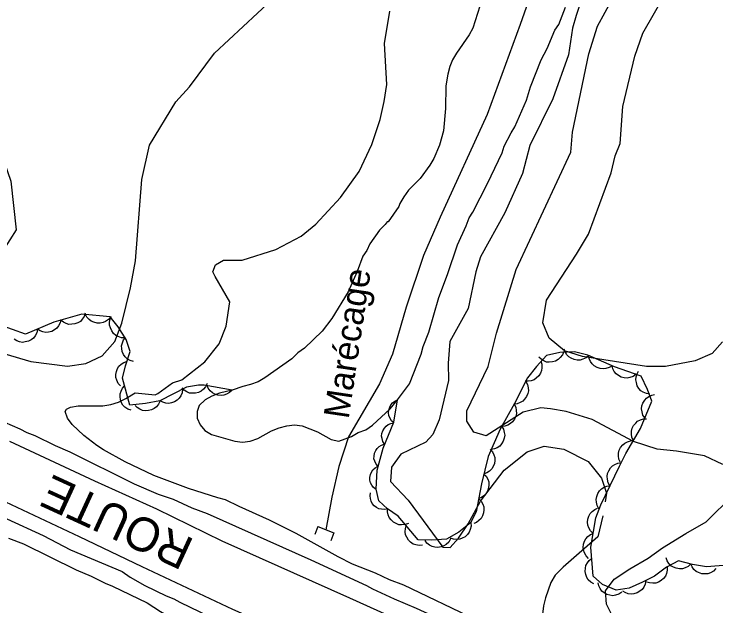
# Model space of a CAD drawing. Extents: x 282461 to 284471, y 5554090 to 5557646.
# Drawn here: x 283897.1 to 283980, y 5554845.7 to 5554915.8 of the extents above; entities that cross this region are included whole.
import ezdxf

# ---------------------------------------------------------------- set-up
doc = ezdxf.new("R2010")
doc.units = 0
for name, color, linetype in [('Niveau 1', 7, 'Continuous'), ('Niveau 15', 7, 'Continuous'), ('Niveau 2', 7, 'Continuous'), ('Niveau 21', 7, 'Continuous'), ('Niveau 26', 7, 'Continuous'), ('Niveau 4', 7, 'Continuous'), ('Niveau 44', 7, 'Continuous'), ('Niveau 7', 7, 'Continuous')]:
    doc.layers.add(name, color=color, linetype=linetype)

msp = doc.modelspace()

# ---------------------------------------------------------------- linework, layer by layer
at = {"layer": 'Niveau 1'}
for points in [[(283980.83, 5554862.48), (283978.67, 5554863.5), (283975.38, 5554864.07), (283973.1, 5554864.3), (283970.27, 5554865.21), (283965.39, 5554867.82), (283962.32, 5554868.73), (283960.5, 5554869.07), (283959.33, 5554869.19), (283957.26, 5554868.66), (283952.89, 5554865.88), (283951.4, 5554866.29), (283950.58, 5554867.62), (283950.61, 5554868.82), (283953.13, 5554874.08), (283954.08, 5554878), (283956.44, 5554885.54), (283962.88, 5554899.43), (283963.09, 5554901.8), (283965.03, 5554911.06), (283966.03, 5554914.34), (283969.64, 5554920.98)], [(283896.01, 5554875.58), (283899.08, 5554874.67), (283903.4, 5554874.1), (283905.57, 5554874.44), (283907.51, 5554875.34), (283909, 5554877.04), (283909.8, 5554879.19), (283910.85, 5554883.38), (283911.44, 5554886.56), (283912.17, 5554896.19), (283913.1, 5554900.26), (283916.2, 5554905.36), (283917.8, 5554907.17), (283920.78, 5554911.13), (283927.53, 5554917.47)], [(283895.94, 5554867.5), (283897.76, 5554866.71), (283898.61, 5554866.26), (283899.52, 5554865.92), (283901.96, 5554864.72), (283903.66, 5554863.99), (283911.27, 5554860.18), (283914.11, 5554858.99), (283915.87, 5554858.37), (283918.09, 5554857.35), (283919.9, 5554856.67), (283932.17, 5554851.22), (283938.75, 5554848.16), (283939.43, 5554847.76), (283941.99, 5554846.57), (283944.6, 5554845.49), (283949.76, 5554843.11), (283956.29, 5554839.94), (283960.54, 5554838.06), (283964.06, 5554836.7), (283969.28, 5554834.21), (283979.55, 5554830.13), (283986.92, 5554826.56)], [(283981.85, 5554840.18), (283979.81, 5554840.74), (283977.19, 5554841.31), (283973.67, 5554841.65), (283971.62, 5554842.11), (283969.13, 5554843.24), (283967.88, 5554844.37), (283967.09, 5554845.96), (283966.99, 5554847.55), (283968.02, 5554848.9), (283969.85, 5554850.15), (283972.01, 5554851.39), (283973.73, 5554852.64), (283976.46, 5554854.33), (283978.86, 5554855.69), (283982.06, 5554858.86)], [(283896.22, 5554856.06), (283900.54, 5554854.07), (283903.77, 5554852.37), (283909.85, 5554849.82), (283910.82, 5554849.14), (283912.52, 5554848.17), (283915.07, 5554846.93), (283915.98, 5554846.59), (283916.66, 5554846.19), (283922.45, 5554843.41)]]:
    msp.add_lwpolyline(points, dxfattribs=at)
at = {"layer": 'Niveau 2'}
for points in [[(283965.09, 5554920.31), (283963.51, 5554915.59), (283963.08, 5554914.09), (283962.61, 5554910.94), (283960.77, 5554905.74), (283958.02, 5554900.2), (283957.18, 5554896.9), (283955.09, 5554892.24), (283952.21, 5554887.06), (283951.64, 5554885.26), (283950.74, 5554880.94), (283948.59, 5554877.01), (283948.4, 5554874.46), (283948.42, 5554872.41), (283947.34, 5554867.78), (283946.56, 5554866.03), (283945.74, 5554865.13), (283942.78, 5554863.69), (283941.69, 5554862.17), (283941.59, 5554860.46), (283943.67, 5554858.26), (283947.75, 5554852.69), (283948.61, 5554852.68), (283949.61, 5554853.75), (283950.75, 5554855.46), (283952.21, 5554858.13), (283955.01, 5554861.79), (283957.71, 5554863.97), (283959.73, 5554864.65), (283962.06, 5554864.29), (283964.94, 5554862.84), (283966.52, 5554860.85), (283967.08, 5554859.08), (283966.94, 5554858.06)], [(283980.82, 5554876.98), (283979.58, 5554875.62), (283977.56, 5554874.73), (283974.06, 5554874.09), (283971.83, 5554874.09), (283964.28, 5554875.26), (283962.15, 5554875.93), (283960.31, 5554877.41), (283959.58, 5554879.25), (283960.01, 5554881.91), (283963.57, 5554887.35), (283964.98, 5554889.71), (283967.65, 5554896.98), (283968.13, 5554898.98), (283968.7, 5554900.43), (283969.03, 5554904.82), (283970.46, 5554910.77), (283971.39, 5554913.5), (283974, 5554918.07)], [(283911.39, 5554870.95), (283913.75, 5554870.72), (283914.07, 5554870.87), (283915.8, 5554872.14), (283916.9, 5554872.48), (283919.63, 5554874.62), (283921.32, 5554876.75), (283922.15, 5554878.86), (283922.59, 5554881.72), (283920.84, 5554884.71), (283920.59, 5554885.28), (283920.9, 5554886.08), (283921.82, 5554886.63), (283924.05, 5554886.63), (283928.01, 5554887.9), (283931, 5554889.47), (283932.75, 5554890.92), (283935.68, 5554894.07), (283937.87, 5554897.14), (283939.38, 5554900.33), (283940.34, 5554903.28), (283940.84, 5554905.42), (283941.15, 5554907.42), (283940.87, 5554912.27), (283941.48, 5554916.11)], [(283896.71, 5554895.98), (283897.34, 5554890.24), (283893.56, 5554884.32), (283891.96, 5554882.87), (283888.71, 5554882), (283886.03, 5554882.4), (283884.77, 5554882.94), (283883.11, 5554884.41), (283880.75, 5554888.18), (283878.69, 5554890.41), (283877.71, 5554891.75), (283877.13, 5554893.38), (283876.99, 5554894.78), (283877.15, 5554895.78), (283879.01, 5554898.91), (283882.64, 5554901.24), (283885.17, 5554902.21), (283886.65, 5554901.81), (283888.67, 5554900.5), (283891.61, 5554900.73), (283894.12, 5554900.14), (283895.53, 5554899.42), (283896.71, 5554895.98)], [(283951.68, 5554844.11), (283943.16, 5554848.19), (283941.46, 5554848.82), (283939.81, 5554849.61), (283937.08, 5554850.69), (283935.38, 5554851.54), (283930.44, 5554854.32), (283927.26, 5554855.91), (283923.68, 5554857.5), (283922.09, 5554858.3), (283921.18, 5554858.52), (283917.71, 5554859.66), (283913.61, 5554861.19), (283910.2, 5554862.78), (283907.65, 5554864.2), (283906.85, 5554864.72), (283905.32, 5554865.91), (283903.96, 5554867.21), (283903.4, 5554867.95), (283903.11, 5554868.74), (283903.29, 5554869.03), (283903.74, 5554869.25), (283904.66, 5554869.42), (283907.56, 5554869.42), (283908.53, 5554869.59), (283909.44, 5554869.87), (283910.3, 5554870.27), (283911.39, 5554870.95)], [(283966.67, 5554856.4), (283966.09, 5554853.92), (283961.96, 5554850.33)], [(283896.43, 5554853.78), (283898.19, 5554853.1), (283904.44, 5554850.03), (283906.2, 5554849.29), (283907.85, 5554848.44), (283908.7, 5554848.1), (283912.8, 5554846.12), (283914.39, 5554845.09), (283916.83, 5554843.67), (283918.53, 5554842.82), (283919.38, 5554842.48), (283920.97, 5554841.63), (283923.36, 5554839.99), (283924.83, 5554838.79)], [(283961.96, 5554850.33), (283961.04, 5554849.37), (283960.52, 5554848.52), (283959.89, 5554846.71), (283959.66, 5554845.75), (283959.54, 5554844.78)]]:
    msp.add_lwpolyline(points, dxfattribs=at)
at = {"layer": 'Niveau 21'}
for points in [[(283896.54, 5554865.24), (283906.59, 5554860.53), (283913.91, 5554857.24), (283921.63, 5554853.44), (283936.73, 5554846.7), (283965.15, 5554833.84), (284014.91, 5554811.14), (284025.97, 5554805.86)], [(283894.01, 5554859.02), (283904.79, 5554853.98), (283912.17, 5554850.4), (283922.9, 5554845.36), (283944.86, 5554835.61), (283957.34, 5554830.35), (283975.37, 5554822.08), (283983.99, 5554818.23), (284000.08, 5554810.69), (284009.04, 5554806.84), (284024.99, 5554799.62)]]:
    msp.add_lwpolyline(points, dxfattribs=at)
at = {"layer": 'Niveau 26'}
for p, q in [((283933, 5554855.13), (283932.63, 5554854.21)), ((283933, 5554855.13), (283934.88, 5554854.4)), ((283934.88, 5554854.4), (283934.51, 5554853.46))]:
    msp.add_line(p, q, dxfattribs=at)
at = {"layer": 'Niveau 4'}
msp.add_lwpolyline([(283962.58, 5554930.64), (283956.91, 5554914.53), (283952.99, 5554903.88), (283947.45, 5554891.74), (283945.49, 5554887.21), (283943.41, 5554881.08), (283941.79, 5554875.53), (283940.29, 5554872.01), (283936.61, 5554865.77), (283935.45, 5554862.26), (283934.63, 5554858.63), (283933.93, 5554854.77)], dxfattribs=at)
at = {"layer": 'Niveau 44'}
for points in [[(283922.84, 5554871.28), (283919.56, 5554871.88), (283918.88, 5554871.88), (283917.46, 5554871.62), (283914.31, 5554870), (283912.62, 5554869.69), (283910.75, 5554869.5), (283909.89, 5554872.69), (283910.26, 5554874.17), (283910.81, 5554875.83), (283910.33, 5554877.26), (283909.38, 5554878.75), (283908.43, 5554879.96), (283905.11, 5554880.27), (283901.8, 5554879.31), (283898.44, 5554877.88), (283895.32, 5554879.01)], [(283905.5, 5554880.38), (283905.38, 5554879.99), (283905.15, 5554879.66), (283904.92, 5554879.41), (283904.62, 5554879.23), (283904.28, 5554879.1), (283903.9, 5554879.06), (283903.57, 5554879.05), (283903.24, 5554879.16), (283902.91, 5554879.32), (283902.63, 5554879.55)], [(283908.5, 5554879.95), (283908.23, 5554879.63), (283907.89, 5554879.41), (283907.6, 5554879.26), (283907.25, 5554879.2), (283906.89, 5554879.21), (283906.52, 5554879.31), (283906.21, 5554879.42), (283905.94, 5554879.64), (283905.69, 5554879.92), (283905.52, 5554880.23)], [(283902.6, 5554879.65), (283902.52, 5554879.24), (283902.33, 5554878.88), (283902.14, 5554878.61), (283901.86, 5554878.4), (283901.53, 5554878.23), (283901.16, 5554878.14), (283900.84, 5554878.1), (283900.5, 5554878.16), (283900.15, 5554878.28), (283899.85, 5554878.48)], [(283910.2, 5554877.47), (283909.78, 5554877.48), (283909.4, 5554877.61), (283909.1, 5554877.75), (283908.84, 5554877.99), (283908.62, 5554878.28), (283908.47, 5554878.64), (283908.38, 5554878.95), (283908.38, 5554879.3), (283908.45, 5554879.66), (283908.59, 5554879.99)], [(283899.85, 5554878.48), (283899.77, 5554878.07), (283899.58, 5554877.71), (283899.39, 5554877.44), (283899.11, 5554877.23), (283898.78, 5554877.06), (283898.41, 5554876.97), (283898.09, 5554876.92), (283897.74, 5554876.99), (283897.4, 5554877.11), (283897.09, 5554877.31)], [(283911.2, 5554874.66), (283910.8, 5554874.77), (283910.46, 5554874.99), (283910.21, 5554875.2), (283910.01, 5554875.49), (283909.87, 5554875.83), (283909.81, 5554876.21), (283909.79, 5554876.53), (283909.88, 5554876.87), (283910.03, 5554877.21), (283910.25, 5554877.5)], [(283965, 5554875.38), (283964.69, 5554875.1), (283964.32, 5554874.93), (283964, 5554874.83), (283963.65, 5554874.83), (283963.28, 5554874.89), (283962.93, 5554875.05), (283962.65, 5554875.21), (283962.41, 5554875.47), (283962.21, 5554875.79), (283962.09, 5554876.13)], [(283982.43, 5554850.65), (283978.93, 5554850.37), (283977.28, 5554850.66), (283975.59, 5554851.07), (283974.17, 5554850.33), (283972.78, 5554849.28), (283971.36, 5554848.58), (283969.76, 5554847.85), (283968.26, 5554847.63), (283966.64, 5554848.28), (283965.52, 5554849.29), (283965.23, 5554852.71), (283965.84, 5554856.16), (283966.42, 5554857.69), (283968.62, 5554862.3), (283969.38, 5554863.78), (283971.13, 5554866.73), (283972.46, 5554869.96), (283971.95, 5554871.37), (283971.18, 5554872.94), (283968.05, 5554874.05), (283964.88, 5554875.41), (283963.32, 5554875.81), (283961.57, 5554875.72), (283960.02, 5554875.37), (283958.83, 5554874.09), (283957.78, 5554872.74), (283956.21, 5554869.68), (283954.53, 5554866.64), (283953.13, 5554863.41), (283952.34, 5554860.19), (283951.68, 5554856.89), (283951.03, 5554855.56), (283949.64, 5554854.49), (283948.18, 5554853.64), (283946.43, 5554853.52), (283944.84, 5554853.56), (283942.48, 5554856.37), (283941.23, 5554857.25)], [(283962.04, 5554875.83), (283961.88, 5554875.44), (283961.63, 5554875.12), (283961.39, 5554874.88), (283961.08, 5554874.72), (283960.73, 5554874.61), (283960.34, 5554874.59), (283960.02, 5554874.6), (283959.69, 5554874.73), (283959.37, 5554874.92), (283959.1, 5554875.16)], [(283967.76, 5554874.17), (283967.41, 5554873.95), (283967.02, 5554873.84), (283966.69, 5554873.79), (283966.34, 5554873.84), (283965.99, 5554873.96), (283965.66, 5554874.17), (283965.41, 5554874.37), (283965.21, 5554874.67), (283965.06, 5554875.01), (283964.99, 5554875.36)], [(283909.66, 5554871.77), (283909.38, 5554872.08), (283909.21, 5554872.45), (283909.11, 5554872.76), (283909.11, 5554873.11), (283909.17, 5554873.47), (283909.32, 5554873.82), (283909.48, 5554874.11), (283909.74, 5554874.34), (283910.05, 5554874.55), (283910.38, 5554874.67)], [(283959.33, 5554874.73), (283959.46, 5554874.33), (283959.46, 5554873.92), (283959.43, 5554873.59), (283959.29, 5554873.27), (283959.09, 5554872.96), (283958.8, 5554872.7), (283958.54, 5554872.5), (283958.21, 5554872.39), (283957.84, 5554872.33), (283957.48, 5554872.35)], [(283970.59, 5554873.15), (283970.25, 5554872.9), (283969.87, 5554872.77), (283969.54, 5554872.7), (283969.19, 5554872.73), (283968.83, 5554872.82), (283968.5, 5554873.01), (283968.23, 5554873.19), (283968.02, 5554873.48), (283967.84, 5554873.81), (283967.75, 5554874.16)], [(283972.23, 5554870.8), (283971.81, 5554870.86), (283971.44, 5554871.03), (283971.16, 5554871.21), (283970.93, 5554871.48), (283970.74, 5554871.79), (283970.63, 5554872.16), (283970.57, 5554872.48), (283970.62, 5554872.83), (283970.72, 5554873.19), (283970.9, 5554873.5)], [(283910.92, 5554868.89), (283910.52, 5554869.02), (283910.19, 5554869.26), (283909.95, 5554869.49), (283909.78, 5554869.79), (283909.65, 5554870.14), (283909.62, 5554870.52), (283909.62, 5554870.84), (283909.73, 5554871.17), (283909.9, 5554871.5), (283910.14, 5554871.77)], [(283919.89, 5554872.06), (283919.72, 5554871.68), (283919.46, 5554871.38), (283919.21, 5554871.16), (283918.89, 5554871.01), (283918.54, 5554870.91), (283918.16, 5554870.9), (283917.83, 5554870.93), (283917.51, 5554871.07), (283917.2, 5554871.27), (283916.95, 5554871.53)], [(283922.84, 5554871.28), (283922.55, 5554870.98), (283922.19, 5554870.79), (283921.89, 5554870.67), (283921.54, 5554870.64), (283921.17, 5554870.68), (283920.81, 5554870.81), (283920.52, 5554870.95), (283920.26, 5554871.19), (283920.04, 5554871.49), (283919.9, 5554871.82)], [(283957.56, 5554872.3), (283957.76, 5554871.94), (283957.84, 5554871.54), (283957.87, 5554871.21), (283957.79, 5554870.86), (283957.65, 5554870.52), (283957.42, 5554870.21), (283957.2, 5554869.97), (283956.89, 5554869.8), (283956.54, 5554869.67), (283956.18, 5554869.63)], [(283917, 5554871.38), (283916.95, 5554870.97), (283916.78, 5554870.6), (283916.61, 5554870.32), (283916.35, 5554870.08), (283916.04, 5554869.88), (283915.67, 5554869.77), (283915.36, 5554869.7), (283915.01, 5554869.74), (283914.65, 5554869.84), (283914.34, 5554870.01)], [(283941.23, 5554857.25), (283940.21, 5554858.19), (283939.88, 5554859.55), (283940, 5554861.82), (283940.7, 5554864.43), (283941.97, 5554867.49), (283942.39, 5554870.11)], [(283941.96, 5554867.4), (283941.68, 5554867.66), (283941.49, 5554867.98), (283941.38, 5554868.26), (283941.34, 5554868.58), (283941.37, 5554868.92), (283941.48, 5554869.25), (283941.61, 5554869.52), (283941.82, 5554869.76), (283942.09, 5554869.97), (283942.39, 5554870.11)], [(283971.64, 5554867.98), (283971.41, 5554868.33), (283971.3, 5554868.72), (283971.24, 5554869.05), (283971.29, 5554869.4), (283971.4, 5554869.75), (283971.61, 5554870.08), (283971.81, 5554870.33), (283972.1, 5554870.53), (283972.44, 5554870.69), (283972.79, 5554870.76)], [(283914.34, 5554870.01), (283914.17, 5554869.62), (283913.91, 5554869.32), (283913.66, 5554869.1), (283913.34, 5554868.95), (283912.99, 5554868.85), (283912.61, 5554868.84), (283912.28, 5554868.87), (283911.96, 5554869.01), (283911.65, 5554869.21), (283911.4, 5554869.47)], [(283956.18, 5554869.63), (283956.37, 5554869.25), (283956.44, 5554868.85), (283956.46, 5554868.52), (283956.37, 5554868.18), (283956.22, 5554867.84), (283955.98, 5554867.54), (283955.75, 5554867.31), (283955.44, 5554867.14), (283955.08, 5554867.03), (283954.72, 5554866.99)], [(283970.28, 5554865.3), (283970.11, 5554865.68), (283970.05, 5554866.09), (283970.04, 5554866.42), (283970.14, 5554866.76), (283970.3, 5554867.09), (283970.55, 5554867.38), (283970.78, 5554867.61), (283971.1, 5554867.76), (283971.46, 5554867.87), (283971.82, 5554867.89)], [(283940.88, 5554864.87), (283940.67, 5554865.19), (283940.57, 5554865.54), (283940.52, 5554865.84), (283940.56, 5554866.16), (283940.67, 5554866.48), (283940.85, 5554866.78), (283941.04, 5554867.02), (283941.3, 5554867.2), (283941.61, 5554867.34), (283941.93, 5554867.4)], [(283954.69, 5554867.01), (283954.92, 5554866.66), (283955.02, 5554866.26), (283955.07, 5554865.94), (283955.02, 5554865.59), (283954.9, 5554865.24), (283954.69, 5554864.91), (283954.48, 5554864.66), (283954.19, 5554864.47), (283953.85, 5554864.32), (283953.49, 5554864.25)], [(283968.75, 5554862.72), (283968.57, 5554863.1), (283968.51, 5554863.5), (283968.51, 5554863.83), (283968.6, 5554864.17), (283968.76, 5554864.5), (283969.01, 5554864.8), (283969.25, 5554865.02), (283969.57, 5554865.18), (283969.92, 5554865.28), (283970.28, 5554865.3)], [(283940.11, 5554862.24), (283939.86, 5554862.53), (283939.71, 5554862.87), (283939.62, 5554863.16), (283939.63, 5554863.48), (283939.68, 5554863.81), (283939.83, 5554864.13), (283939.98, 5554864.39), (283940.22, 5554864.6), (283940.51, 5554864.78), (283940.82, 5554864.89)], [(283953.35, 5554864.3), (283953.63, 5554863.99), (283953.8, 5554863.62), (283953.9, 5554863.3), (283953.91, 5554862.95), (283953.85, 5554862.58), (283953.7, 5554862.23), (283953.54, 5554861.95), (283953.28, 5554861.71), (283952.97, 5554861.5), (283952.63, 5554861.38)], [(283967.51, 5554859.97), (283967.3, 5554860.33), (283967.2, 5554860.73), (283967.17, 5554861.06), (283967.23, 5554861.4), (283967.36, 5554861.75), (283967.58, 5554862.07), (283967.8, 5554862.31), (283968.1, 5554862.49), (283968.45, 5554862.63), (283968.8, 5554862.69)], [(283939.88, 5554859.51), (283939.57, 5554859.74), (283939.35, 5554860.04), (283939.21, 5554860.31), (283939.14, 5554860.62), (283939.13, 5554860.96), (283939.21, 5554861.3), (283939.31, 5554861.59), (283939.5, 5554861.84), (283939.74, 5554862.08), (283940.02, 5554862.25)], [(283952.58, 5554861.39), (283952.87, 5554861.09), (283953.06, 5554860.73), (283953.18, 5554860.42), (283953.2, 5554860.06), (283953.16, 5554859.7), (283953.02, 5554859.34), (283952.87, 5554859.05), (283952.62, 5554858.79), (283952.32, 5554858.58), (283951.99, 5554858.44)], [(283966.21, 5554857.25), (283966, 5554857.62), (283965.9, 5554858.01), (283965.87, 5554858.34), (283965.94, 5554858.69), (283966.07, 5554859.04), (283966.29, 5554859.35), (283966.5, 5554859.6), (283966.81, 5554859.78), (283967.15, 5554859.92), (283967.51, 5554859.97)], [(283941.23, 5554857.25), (283940.86, 5554857.16), (283940.49, 5554857.19), (283940.19, 5554857.25), (283939.91, 5554857.4), (283939.64, 5554857.6), (283939.42, 5554857.88), (283939.27, 5554858.13), (283939.19, 5554858.45), (283939.16, 5554858.78), (283939.21, 5554859.11)], [(283951.99, 5554858.44), (283952.28, 5554858.14), (283952.47, 5554857.78), (283952.59, 5554857.47), (283952.61, 5554857.11), (283952.57, 5554856.75), (283952.43, 5554856.39), (283952.28, 5554856.1), (283952.03, 5554855.84), (283951.73, 5554855.63), (283951.4, 5554855.49)], [(283943.69, 5554855.52), (283943.3, 5554855.37), (283942.89, 5554855.34), (283942.56, 5554855.36), (283942.23, 5554855.49), (283941.91, 5554855.67), (283941.64, 5554855.94), (283941.43, 5554856.2), (283941.3, 5554856.53), (283941.22, 5554856.89), (283941.23, 5554857.25)], [(283965.52, 5554854.33), (283965.22, 5554854.62), (283965.02, 5554854.98), (283964.9, 5554855.29), (283964.87, 5554855.64), (283964.9, 5554856.01), (283965.03, 5554856.37), (283965.17, 5554856.67), (283965.41, 5554856.92), (283965.71, 5554857.15), (283966.04, 5554857.3)], [(283945.37, 5554852.93), (283944.95, 5554852.89), (283944.55, 5554852.97), (283944.24, 5554853.07), (283943.95, 5554853.28), (283943.69, 5554853.54), (283943.49, 5554853.87), (283943.36, 5554854.17), (283943.32, 5554854.52), (283943.33, 5554854.89), (283943.43, 5554855.24)], [(283951.07, 5554855.59), (283951.09, 5554855.17), (283951, 5554854.78), (283950.88, 5554854.47), (283950.67, 5554854.19), (283950.39, 5554853.94), (283950.05, 5554853.76), (283949.75, 5554853.63), (283949.4, 5554853.61), (283949.03, 5554853.64), (283948.68, 5554853.75)], [(283964.99, 5554851.37), (283964.69, 5554851.66), (283964.49, 5554852.02), (283964.37, 5554852.33), (283964.34, 5554852.68), (283964.38, 5554853.05), (283964.51, 5554853.41), (283964.65, 5554853.7), (283964.89, 5554853.96), (283965.19, 5554854.19), (283965.52, 5554854.33)], [(283948.66, 5554853.67), (283948.45, 5554853.31), (283948.15, 5554853.03), (283947.88, 5554852.84), (283947.55, 5554852.73), (283947.18, 5554852.67), (283946.8, 5554852.71), (283946.48, 5554852.78), (283946.17, 5554852.95), (283945.88, 5554853.18), (283945.66, 5554853.47)], [(283965.6, 5554848.36), (283965.23, 5554848.56), (283964.95, 5554848.85), (283964.76, 5554849.12), (283964.64, 5554849.45), (283964.57, 5554849.82), (283964.61, 5554850.2), (283964.67, 5554850.52), (283964.84, 5554850.83), (283965.06, 5554851.13), (283965.34, 5554851.35)], [(283977.07, 5554850.71), (283976.76, 5554850.43), (283976.39, 5554850.26), (283976.07, 5554850.15), (283975.72, 5554850.15), (283975.35, 5554850.2), (283975, 5554850.35), (283974.71, 5554850.51), (283974.47, 5554850.77), (283974.27, 5554851.08), (283974.14, 5554851.42)], [(283974.26, 5554850.4), (283974.28, 5554849.98), (283974.18, 5554849.58), (283974.06, 5554849.27), (283973.84, 5554849), (283973.57, 5554848.75), (283973.23, 5554848.57), (283972.92, 5554848.45), (283972.57, 5554848.43), (283972.2, 5554848.47), (283971.86, 5554848.58)], [(283980.03, 5554850.18), (283979.73, 5554849.88), (283979.38, 5554849.68), (283979.07, 5554849.56), (283978.72, 5554849.53), (283978.35, 5554849.56), (283977.99, 5554849.69), (283977.69, 5554849.83), (283977.43, 5554850.07), (283977.21, 5554850.37), (283977.06, 5554850.7)], [(283968.9, 5554847.37), (283968.56, 5554847.14), (283968.17, 5554847.02), (283967.84, 5554846.96), (283967.49, 5554847.01), (283967.13, 5554847.11), (283966.81, 5554847.31), (283966.55, 5554847.51), (283966.35, 5554847.8), (283966.19, 5554848.14), (283966.11, 5554848.49)], [(283971.75, 5554848.76), (283971.68, 5554848.34), (283971.5, 5554847.98), (283971.31, 5554847.7), (283971.04, 5554847.48), (283970.72, 5554847.3), (283970.34, 5554847.2), (283970.02, 5554847.15), (283969.67, 5554847.2), (283969.32, 5554847.32), (283969.01, 5554847.51)]]:
    msp.add_lwpolyline(points, dxfattribs=at)
at = {"layer": 'Niveau 7'}
for points in [[(283938.31, 5554887.12), (283937.62, 5554885.3), (283936.58, 5554882.92), (283934.63, 5554879.75), (283933.48, 5554878.27), (283931.42, 5554876.23), (283930.62, 5554875.67), (283929.93, 5554874.99), (283926.73, 5554872.72), (283925.93, 5554872.27), (283925.01, 5554871.93), (283924.1, 5554871.7), (283922.84, 5554871.28), (283921.36, 5554870.91), (283920.45, 5554870.57), (283919.65, 5554870.12), (283918.96, 5554869.44), (283918.73, 5554868.76), (283918.72, 5554867.96), (283919.06, 5554867.17), (283919.63, 5554866.49), (283920.42, 5554866.03), (283923.16, 5554865.24), (283924.07, 5554865.12), (283924.98, 5554865.24), (283925.89, 5554865.57), (283927.49, 5554866.48), (283928.41, 5554866.82), (283929.32, 5554867.05), (283930.23, 5554867.16), (283931.14, 5554867.05), (283932.96, 5554866.36), (283934.55, 5554865.45), (283935.46, 5554865.23), (283936.95, 5554865.79), (283937.75, 5554866.25), (283938.66, 5554866.59), (283939.46, 5554867.15), (283941.52, 5554869.08), (283942.39, 5554870.11), (283943.81, 5554872.03), (283945.2, 5554875.54), (283945.43, 5554876.45), (283946.12, 5554878.15), (283947.28, 5554882.23), (283948.32, 5554884.95), (283949.48, 5554888.47), (283950.52, 5554890.73), (283950.86, 5554891.64), (283951.32, 5554892.32), (283953.05, 5554895.72), (283954.78, 5554899.35), (283955.01, 5554900.14), (283955.82, 5554901.73), (283956.27, 5554902.41), (283957.66, 5554905.58), (283958.12, 5554907.17), (283959.39, 5554910.34), (283960.08, 5554911.7), (283961, 5554913.86), (283961.46, 5554914.54), (283962.27, 5554916.58)], [(283952.13, 5554916.7), (283951.32, 5554914.1), (283950.86, 5554913.3), (283949.37, 5554911.15), (283948.91, 5554910.36), (283948.57, 5554909.56), (283948.33, 5554908.66), (283948.1, 5554907.29), (283948.08, 5554904.57), (283947.84, 5554901.96), (283947.38, 5554900.26), (283946.69, 5554898.68), (283946.23, 5554897.88), (283945.08, 5554896.3), (283943.71, 5554894.94), (283943.13, 5554894.14), (283942.67, 5554893.35), (283942.56, 5554893.01), (283941.29, 5554891.2), (283941.18, 5554891.2), (283940.95, 5554890.86), (283940.26, 5554890.18), (283939.11, 5554888.59), (283938.77, 5554887.8), (283938.31, 5554887.12)]]:
    msp.add_lwpolyline(points, dxfattribs=at)

# ---------------------------------------------------------------- texts
at = {"layer": 'Niveau 15'}
msp.add_text('ROUTE', height=4, rotation=155.30959, dxfattribs=at).set_placement((283918.55, 5554853.55))
at = {"layer": 'Niveau 7'}
msp.add_text('Marécage', height=2.9999, rotation=81.51387, dxfattribs=at).set_placement((283936.62, 5554867.78))

doc.saveas('drawing.dxf')
